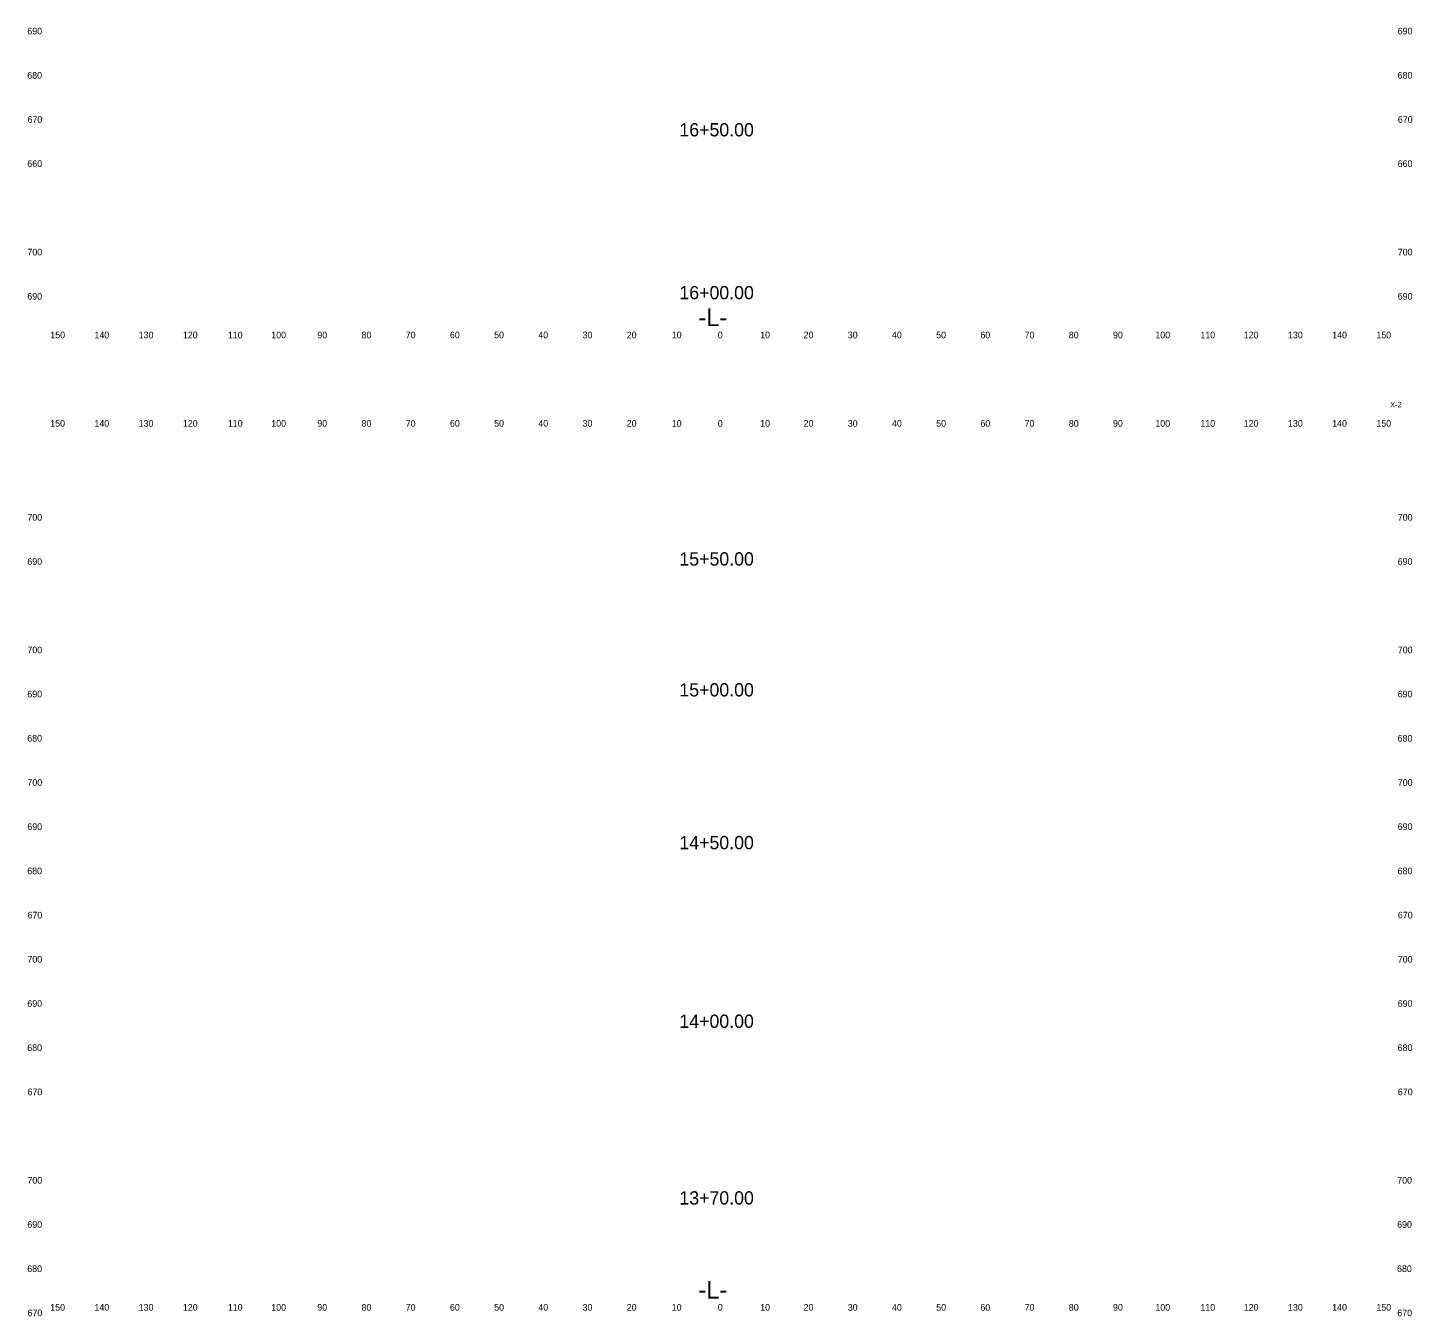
# Model space of a CAD drawing. Extents: x 3 to 317, y 0 to 2407.
# Drawn here: x 3.3 to 316.6, y 0 to 291.5 of the extents above; entities that cross this region are included whole.
import ezdxf

# ---------------------------------------------------------------- set-up
doc = ezdxf.new("R2010")
doc.units = 0
for name, color, linetype in [('Prop XS Ditch Standard Text', 7, 'Continuous'), ('Prop XS Dump Level', 7, 'Continuous'), ('Prop XS SE Text', 7, 'Continuous'), ('Prop XS Sheet Number', 7, 'Continuous'), ('Prop XS SS Elevation Text', 7, 'Continuous')]:
    doc.layers.add(name, color=color, linetype=linetype)

msp = doc.modelspace()

# ---------------------------------------------------------------- texts
at = {"layer": 'Prop XS Ditch Standard Text'}
for s, p in [('16+50.00', (150.77, 266.93)), ('16+00.00', (150.77, 230.08)), ('15+50.00', (150.77, 169.84)), ('15+00.00', (150.77, 140.22)), ('14+50.00', (150.77, 105.66)), ('14+00.00', (150.77, 65.24)), ('13+70.00', (150.77, 25.27))]:
    msp.add_text(s, height=3, dxfattribs=at).set_placement(p)
at = {"layer": 'Prop XS Dump Level'}
for s, p in [('150', (8.44, 221.25)), ('140', (18.44, 221.25)), ('130', (28.44, 221.25)), ('120', (38.44, 221.25)), ('110', (48.62, 221.25)), ('100', (58.44, 221.25)), ('90', (68.86, 221.25)), ('80', (78.86, 221.25)), ('70', (88.86, 221.25)), ('60', (98.86, 221.25)), ('50', (108.86, 221.25)), ('40', (118.86, 221.25)), ('30', (128.86, 221.25)), ('20', (138.86, 221.25)), ('10', (149.04, 221.25)), ('0', (159.45, 221.25)), ('10', (169.04, 221.25)), ('20', (178.86, 221.25)), ('30', (188.86, 221.25)), ('40', (198.86, 221.25)), ('50', (208.86, 221.25)), ('60', (218.86, 221.25)), ('70', (228.86, 221.25)), ('80', (238.86, 221.25)), ('90', (248.86, 221.25)), ('100', (258.44, 221.25)), ('110', (268.62, 221.25)), ('120', (278.44, 221.25)), ('130', (288.44, 221.25)), ('140', (298.44, 221.25)), ('150', (308.44, 221.25)), ('150', (8.44, 201.25)), ('140', (18.44, 201.25)), ('130', (28.44, 201.25)), ('120', (38.44, 201.25)), ('110', (48.62, 201.25)), ('100', (58.44, 201.25)), ('90', (68.86, 201.25)), ('80', (78.86, 201.25)), ('70', (88.86, 201.25)), ('60', (98.86, 201.25)), ('50', (108.86, 201.25)), ('40', (118.86, 201.25)), ('30', (128.86, 201.25)), ('20', (138.86, 201.25)), ('10', (149.04, 201.25)), ('0', (159.45, 201.25)), ('10', (169.04, 201.25)), ('20', (178.86, 201.25)), ('30', (188.86, 201.25)), ('40', (198.86, 201.25)), ('50', (208.86, 201.25)), ('60', (218.86, 201.25)), ('70', (228.86, 201.25)), ('80', (238.86, 201.25)), ('90', (248.86, 201.25)), ('100', (258.44, 201.25)), ('110', (268.62, 201.25)), ('120', (278.44, 201.25)), ('130', (288.44, 201.25)), ('140', (298.44, 201.25)), ('150', (308.44, 201.25)), ('150', (8.44, 1.25)), ('140', (18.44, 1.25)), ('130', (28.44, 1.25)), ('120', (38.44, 1.25)), ('110', (48.62, 1.25)), ('100', (58.44, 1.25)), ('90', (68.86, 1.25)), ('80', (78.86, 1.25)), ('70', (88.86, 1.25)), ('60', (98.86, 1.25)), ('50', (108.86, 1.25)), ('40', (118.86, 1.25)), ('30', (128.86, 1.25)), ('20', (138.86, 1.25)), ('10', (149.04, 1.25)), ('0', (159.45, 1.25)), ('10', (169.04, 1.25)), ('20', (178.86, 1.25)), ('30', (188.86, 1.25)), ('40', (198.86, 1.25)), ('50', (208.86, 1.25)), ('60', (218.86, 1.25)), ('70', (228.86, 1.25)), ('80', (238.86, 1.25)), ('90', (248.86, 1.25)), ('100', (258.44, 1.25)), ('110', (268.62, 1.25)), ('120', (278.44, 1.25)), ('130', (288.44, 1.25)), ('140', (298.44, 1.25)), ('150', (308.44, 1.25))]:
    msp.add_text(s, height=1.5, dxfattribs=at).set_placement(p)
at = {"layer": 'Prop XS SE Text'}
for s, p in [('690', (3.26, 290)), ('690', (313.26, 290)), ('680', (3.24, 280)), ('680', (313.24, 280)), ('670', (3.3, 270)), ('670', (313.3, 270)), ('660', (3.26, 260)), ('660', (313.26, 260)), ('700', (3.28, 240)), ('700', (313.28, 240)), ('690', (3.26, 230)), ('690', (313.26, 230)), ('700', (3.28, 180)), ('700', (313.28, 180)), ('690', (3.26, 170)), ('690', (313.26, 170)), ('700', (3.28, 150)), ('700', (313.28, 150)), ('690', (3.26, 140)), ('690', (313.26, 140)), ('680', (3.24, 130)), ('680', (313.24, 130)), ('700', (3.28, 120)), ('700', (313.28, 120)), ('690', (3.26, 110)), ('690', (313.26, 110)), ('680', (3.24, 100)), ('680', (313.24, 100)), ('670', (3.3, 90)), ('670', (313.3, 90)), ('700', (3.28, 80)), ('700', (313.28, 80)), ('690', (3.26, 70)), ('690', (313.26, 70)), ('680', (3.24, 60)), ('680', (313.24, 60)), ('670', (3.3, 50)), ('670', (313.3, 50)), ('700', (3.28, 30)), ('700', (313.15, 30)), ('690', (3.26, 20)), ('690', (313.14, 20)), ('680', (3.24, 10)), ('680', (313.11, 10)), ('670', (3.3, 0)), ('670', (313.17, 0))]:
    msp.add_text(s, height=1.5, dxfattribs=at).set_placement(p)
at = {"layer": 'Prop XS Sheet Number'}
msp.add_text('X-2', height=1.25, dxfattribs=at).set_placement((311.56, 205.61))
at = {"layer": 'Prop XS SS Elevation Text'}
for p in [(155.06, 224), (155.06, 4)]:
    msp.add_text('-L-', height=4, dxfattribs=at).set_placement(p)

doc.saveas('drawing.dxf')
